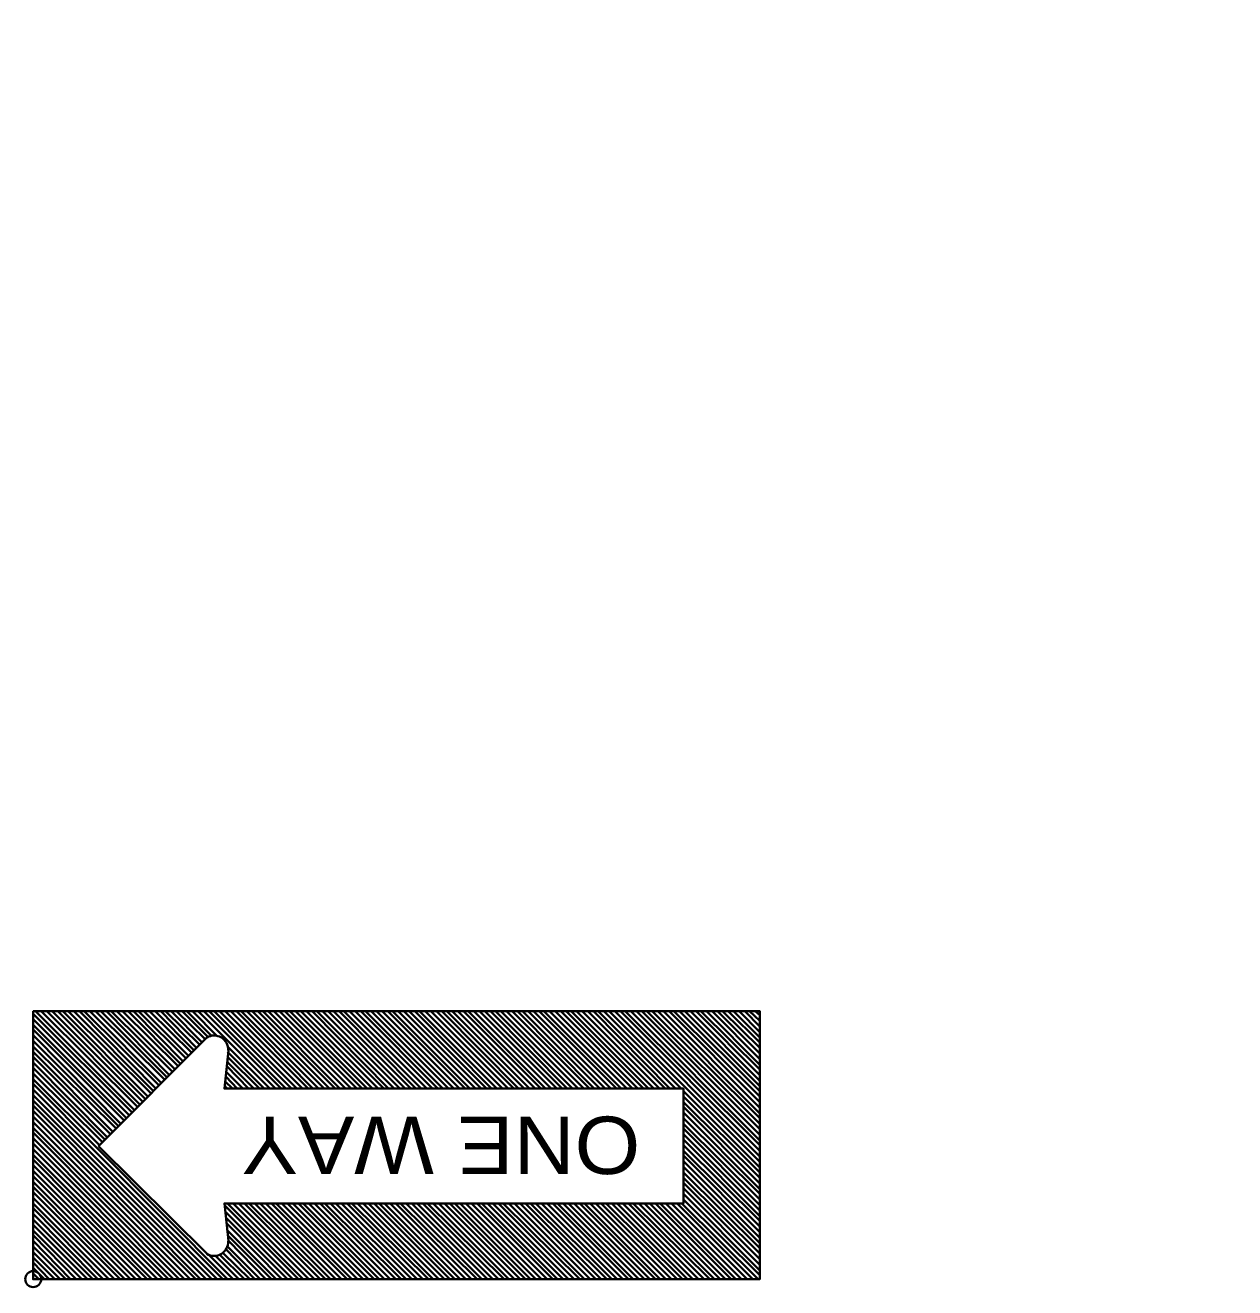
# Model space of a CAD drawing. Extents: x -133 to 547, y -328 to 112.
# Drawn here: x -42.67 to -12.31, y 0.3 to 31.98 of the extents above; entities that cross this region are included whole.
import ezdxf
from ezdxf.enums import TextEntityAlignment as Align

# ---------------------------------------------------------------- set-up
doc = ezdxf.new("R2010")
doc.units = 0
doc.header["$LTSCALE"] = 0.8
doc.header["$PDMODE"] = 32
doc.header["$PDSIZE"] = 0.4
doc.layers.add('1', color=7, linetype='Continuous', lineweight=35)

msp = doc.modelspace()

# ---------------------------------------------------------------- linework, layer by layer
at = {"layer": '1'}
for p, q in [((-42.474, 7.1764), (-39.994, 4.6964)), ((-42.474, 7.0364), (-40.074, 4.6364)), ((-42.414, 7.2364), (-39.934, 4.7564)), ((-42.274, 7.2364), (-39.854, 4.8364)), ((-42.134, 7.2364), (-39.794, 4.8964)), ((-41.994, 7.2364), (-39.734, 4.9764)), ((-41.854, 7.2364), (-39.654, 5.0364)), ((-41.734, 7.2364), (-39.594, 5.0964)), ((-41.594, 7.2364), (-39.514, 5.1764)), ((-41.454, 7.2364), (-39.454, 5.2364)), ((-41.314, 7.2364), (-39.394, 5.2964)), ((-41.194, 7.2364), (-39.314, 5.3764)), ((-41.054, 7.2364), (-39.254, 5.4364)), ((-40.914, 7.2364), (-39.174, 5.5164)), ((-40.774, 7.2364), (-39.114, 5.5764)), ((-40.634, 7.2364), (-39.054, 5.6364)), ((-40.514, 7.2364), (-38.974, 5.7164)), ((-40.374, 7.2364), (-38.914, 5.7764)), ((-40.234, 7.2364), (-38.834, 5.8564)), ((-40.094, 7.2364), (-38.774, 5.9164)), ((-39.954, 7.2364), (-38.714, 5.9764)), ((-39.834, 7.2364), (-38.634, 6.0564)), ((-39.694, 7.2364), (-38.574, 6.1164)), ((-39.554, 7.2364), (-38.494, 6.1964)), ((-39.414, 7.2364), (-38.434, 6.2564)), ((-39.274, 7.2364), (-38.374, 6.3164)), ((-39.154, 7.2364), (-38.294, 6.3964)), ((-39.014, 7.2364), (-38.234, 6.4564)), ((-38.874, 7.2364), (-38.154, 6.5364)), ((-38.734, 7.2364), (-38.094, 6.5964)), ((-38.614, 7.2364), (-37.994, 6.6164)), ((-38.474, 7.2364), (-37.854, 6.6164)), ((-38.334, 7.2364), (-36.394, 5.2964)), ((-38.194, 7.2364), (-36.254, 5.2964)), ((-38.054, 7.2364), (-36.134, 5.2964)), ((-37.934, 7.2364), (-35.994, 5.2964)), ((-37.794, 7.2364), (-35.854, 5.2964)), ((-37.654, 7.2364), (-35.714, 5.2964)), ((-37.514, 7.2364), (-35.574, 5.2964)), ((-37.374, 7.2364), (-35.454, 5.2964)), ((-37.254, 7.2364), (-35.314, 5.2964)), ((-37.114, 7.2364), (-35.174, 5.2964)), ((-36.974, 7.2364), (-35.034, 5.2964)), ((-36.834, 7.2364), (-34.894, 5.2964)), ((-36.714, 7.2364), (-34.774, 5.2964)), ((-36.574, 7.2364), (-34.634, 5.2964)), ((-36.434, 7.2364), (-34.494, 5.2964)), ((-36.294, 7.2364), (-34.354, 5.2964)), ((-36.154, 7.2364), (-34.214, 5.2964)), ((-36.034, 7.2364), (-34.094, 5.2964)), ((-35.894, 7.2364), (-33.954, 5.2964)), ((-35.754, 7.2364), (-33.814, 5.2964)), ((-35.614, 7.2364), (-33.674, 5.2964)), ((-35.474, 7.2364), (-33.554, 5.2964)), ((-35.354, 7.2364), (-33.414, 5.2964)), ((-35.214, 7.2364), (-33.274, 5.2964)), ((-35.074, 7.2364), (-33.134, 5.2964)), ((-34.934, 7.2364), (-32.994, 5.2964)), ((-34.794, 7.2364), (-32.874, 5.2964)), ((-34.674, 7.2364), (-32.734, 5.2964)), ((-34.534, 7.2364), (-32.594, 5.2964)), ((-34.394, 7.2364), (-32.454, 5.2964)), ((-34.254, 7.2364), (-32.314, 5.2964)), ((-34.134, 7.2364), (-32.194, 5.2964)), ((-33.994, 7.2364), (-32.054, 5.2964)), ((-33.854, 7.2364), (-31.914, 5.2964)), ((-33.714, 7.2364), (-31.774, 5.2964)), ((-33.574, 7.2364), (-31.634, 5.2964)), ((-33.454, 7.2364), (-31.514, 5.2964)), ((-33.314, 7.2364), (-31.374, 5.2964)), ((-33.174, 7.2364), (-31.234, 5.2964)), ((-33.034, 7.2364), (-31.094, 5.2964)), ((-32.894, 7.2364), (-30.974, 5.2964)), ((-32.774, 7.2364), (-30.834, 5.2964)), ((-32.634, 7.2364), (-30.694, 5.2964)), ((-32.494, 7.2364), (-30.554, 5.2964)), ((-32.354, 7.2364), (-30.414, 5.2964)), ((-32.214, 7.2364), (-30.294, 5.2964)), ((-32.094, 7.2364), (-30.154, 5.2964)), ((-31.954, 7.2364), (-30.014, 5.2964)), ((-31.814, 7.2364), (-29.874, 5.2964)), ((-31.674, 7.2364), (-29.734, 5.2964)), ((-31.554, 7.2364), (-29.614, 5.2964)), ((-31.414, 7.2364), (-29.474, 5.2964)), ((-31.274, 7.2364), (-29.334, 5.2964)), ((-31.134, 7.2364), (-29.194, 5.2964)), ((-30.994, 7.2364), (-29.074, 5.2964)), ((-30.874, 7.2364), (-28.934, 5.2964)), ((-30.734, 7.2364), (-28.794, 5.2964)), ((-30.594, 7.2364), (-28.654, 5.2964)), ((-30.454, 7.2364), (-28.514, 5.2964)), ((-30.314, 7.2364), (-28.394, 5.2964)), ((-30.194, 7.2364), (-28.254, 5.2964)), ((-30.054, 7.2364), (-28.114, 5.2964)), ((-29.914, 7.2364), (-27.974, 5.2964)), ((-29.774, 7.2364), (-27.834, 5.2964)), ((-29.654, 7.2364), (-27.714, 5.2964)), ((-29.514, 7.2364), (-27.574, 5.2964)), ((-29.374, 7.2364), (-27.434, 5.2964)), ((-29.234, 7.2364), (-27.294, 5.2964)), ((-29.094, 7.2364), (-27.154, 5.2964)), ((-28.974, 7.2364), (-27.034, 5.2964)), ((-28.834, 7.2364), (-26.894, 5.2964)), ((-28.694, 7.2364), (-26.754, 5.2964)), ((-28.554, 7.2364), (-26.614, 5.2964)), ((-28.414, 7.2364), (-26.494, 5.2964)), ((-28.294, 7.2364), (-26.354, 5.2964)), ((-28.154, 7.2364), (-26.214, 5.2964)), ((-28.014, 7.2364), (-24.234, 3.4564)), ((-27.874, 7.2364), (-24.234, 3.5964)), ((-27.734, 7.2364), (-24.234, 3.7364)), ((-27.614, 7.2364), (-24.234, 3.8764)), ((-27.474, 7.2364), (-24.234, 3.9964)), ((-27.334, 7.2364), (-24.234, 4.1364)), ((-27.194, 7.2364), (-24.234, 4.2764)), ((-27.074, 7.2364), (-24.234, 4.4164)), ((-26.934, 7.2364), (-24.234, 4.5564)), ((-26.794, 7.2364), (-24.234, 4.6764)), ((-26.654, 7.2364), (-24.234, 4.8164)), ((-26.514, 7.2364), (-24.234, 4.9564)), ((-26.394, 7.2364), (-24.234, 5.0964)), ((-26.254, 7.2364), (-24.234, 5.2364)), ((-26.114, 7.2364), (-24.234, 5.3564)), ((-25.974, 7.2364), (-24.234, 5.4964)), ((-25.834, 7.2364), (-24.234, 5.6364)), ((-25.714, 7.2364), (-24.234, 5.7764)), ((-25.574, 7.2364), (-24.234, 5.8964)), ((-25.434, 7.2364), (-24.234, 6.0364)), ((-25.294, 7.2364), (-24.234, 6.1764)), ((-25.174, 7.2364), (-24.234, 6.3164)), ((-25.034, 7.2364), (-24.234, 6.4564)), ((-24.894, 7.2364), (-24.234, 6.5764)), ((-24.754, 7.2364), (-24.234, 6.7164)), ((-24.614, 7.2364), (-24.234, 6.8564)), ((-24.494, 7.2364), (-24.234, 6.9964)), ((-24.354, 7.2364), (-24.234, 7.1364)), ((-42.474, 6.8964), (-40.134, 4.5564)), ((-42.474, 6.7764), (-40.194, 4.4964)), ((-42.474, 6.6364), (-40.274, 4.4164)), ((-42.474, 6.4964), (-40.334, 4.3564)), ((-42.474, 6.3564), (-40.394, 4.2964)), ((-38.114, 6.5764), (-40.834, 3.8564)), ((-37.594, 6.3564), (-36.534, 5.2964)), ((-42.474, 6.2164), (-40.474, 4.2164)), ((-42.474, 6.0964), (-40.534, 4.1564)), ((-37.594, 6.2164), (-36.674, 5.2964)), ((-37.594, 6.0964), (-36.794, 5.2964)), ((-42.474, 5.9564), (-40.614, 4.0764)), ((-42.474, 5.8164), (-40.674, 4.0164)), ((-37.634, 5.7164), (-37.214, 5.2964)), ((-37.614, 5.9764), (-36.934, 5.2964)), ((-37.614, 5.8564), (-37.074, 5.2964)), ((-42.474, 5.6764), (-40.734, 3.9564)), ((-42.474, 5.5364), (-40.814, 3.8764)), ((-42.474, 5.4164), (-37.594, 0.5164)), ((-37.654, 5.4764), (-37.474, 5.2964)), ((-37.634, 5.5964), (-37.354, 5.2964)), ((-42.474, 5.2764), (-37.714, 0.5164)), ((-42.474, 5.1364), (-37.854, 0.5164)), ((-37.654, 5.3564), (-37.614, 5.2964)), ((-26.154, 5.2364), (-24.234, 3.3164)), ((-26.154, 5.0964), (-24.234, 3.1964)), ((-42.474, 4.9964), (-37.994, 0.5164)), ((-42.474, 4.8764), (-38.134, 0.5164)), ((-26.154, 4.9564), (-24.234, 3.0564)), ((-26.154, 4.8364), (-24.234, 2.9164)), ((-42.474, 4.7364), (-38.274, 0.5164)), ((-42.474, 4.5964), (-38.394, 0.5164)), ((-42.474, 4.4564), (-38.534, 0.5164)), ((-26.154, 4.6964), (-24.234, 2.7764)), ((-26.154, 4.5564), (-24.234, 2.6564)), ((-42.474, 4.3164), (-38.674, 0.5164)), ((-42.474, 4.1964), (-38.814, 0.5164)), ((-26.154, 4.4164), (-24.234, 2.5164)), ((-26.154, 4.2964), (-24.234, 2.3764)), ((-26.154, 4.1564), (-24.234, 2.2364)), ((-42.474, 4.0564), (-38.954, 0.5164)), ((-42.474, 3.9164), (-39.074, 0.5164)), ((-40.834, 3.8564), (-38.114, 1.1564)), ((-26.154, 4.0164), (-24.234, 2.0964)), ((-26.154, 3.8764), (-24.234, 1.9764)), ((-42.474, 3.7764), (-39.214, 0.5164)), ((-42.474, 3.6364), (-39.354, 0.5164)), ((-42.474, 3.5164), (-39.494, 0.5164)), ((-26.154, 3.7364), (-24.234, 1.8364)), ((-26.154, 3.6164), (-24.234, 1.6964)), ((-42.474, 3.3764), (-39.614, 0.5164)), ((-42.474, 3.2364), (-39.754, 0.5164)), ((-26.154, 3.4764), (-24.234, 1.5564)), ((-26.154, 3.3364), (-24.234, 1.4164)), ((-26.154, 3.1964), (-24.234, 1.2964)), ((-42.474, 3.0964), (-39.894, 0.5164)), ((-42.474, 2.9564), (-40.034, 0.5164)), ((-26.154, 3.0564), (-24.234, 1.1564)), ((-26.154, 2.9364), (-24.234, 1.0164)), ((-42.474, 2.8364), (-40.174, 0.5164)), ((-42.474, 2.6964), (-40.294, 0.5164)), ((-42.474, 2.5564), (-40.434, 0.5164)), ((-26.154, 2.7964), (-24.234, 0.8764)), ((-26.154, 2.6564), (-24.234, 0.7364)), ((-42.474, 2.4164), (-40.574, 0.5164)), ((-42.474, 2.2964), (-40.714, 0.5164)), ((-37.654, 2.3564), (-35.814, 0.5164)), ((-37.594, 2.4164), (-35.694, 0.5164)), ((-37.454, 2.4164), (-35.554, 0.5164)), ((-37.314, 2.4164), (-35.414, 0.5164)), ((-37.174, 2.4164), (-35.274, 0.5164)), ((-37.054, 2.4164), (-35.134, 0.5164)), ((-36.914, 2.4164), (-35.014, 0.5164)), ((-36.774, 2.4164), (-34.874, 0.5164)), ((-36.634, 2.4164), (-34.734, 0.5164)), ((-36.494, 2.4164), (-34.594, 0.5164)), ((-36.374, 2.4164), (-34.474, 0.5164)), ((-36.234, 2.4164), (-34.334, 0.5164)), ((-36.094, 2.4164), (-34.194, 0.5164)), ((-35.954, 2.4164), (-34.054, 0.5164)), ((-35.814, 2.4164), (-33.914, 0.5164)), ((-35.694, 2.4164), (-33.794, 0.5164)), ((-35.554, 2.4164), (-33.654, 0.5164)), ((-35.414, 2.4164), (-33.514, 0.5164)), ((-35.274, 2.4164), (-33.374, 0.5164)), ((-35.154, 2.4164), (-33.234, 0.5164)), ((-35.014, 2.4164), (-33.114, 0.5164)), ((-34.874, 2.4164), (-32.974, 0.5164)), ((-34.734, 2.4164), (-32.834, 0.5164)), ((-34.594, 2.4164), (-32.694, 0.5164)), ((-34.474, 2.4164), (-32.554, 0.5164)), ((-34.334, 2.4164), (-32.434, 0.5164)), ((-34.194, 2.4164), (-32.294, 0.5164)), ((-34.054, 2.4164), (-32.154, 0.5164)), ((-33.914, 2.4164), (-32.014, 0.5164)), ((-33.794, 2.4164), (-31.894, 0.5164)), ((-33.654, 2.4164), (-31.754, 0.5164)), ((-33.514, 2.4164), (-31.614, 0.5164)), ((-33.374, 2.4164), (-31.474, 0.5164)), ((-33.254, 2.4164), (-31.334, 0.5164)), ((-33.114, 2.4164), (-31.214, 0.5164)), ((-32.974, 2.4164), (-31.074, 0.5164)), ((-32.834, 2.4164), (-30.934, 0.5164)), ((-32.694, 2.4164), (-30.794, 0.5164)), ((-32.574, 2.4164), (-30.654, 0.5164)), ((-32.434, 2.4164), (-30.534, 0.5164)), ((-32.294, 2.4164), (-30.394, 0.5164)), ((-32.154, 2.4164), (-30.254, 0.5164)), ((-32.014, 2.4164), (-30.114, 0.5164)), ((-31.894, 2.4164), (-29.994, 0.5164)), ((-31.754, 2.4164), (-29.854, 0.5164)), ((-31.614, 2.4164), (-29.714, 0.5164)), ((-31.474, 2.4164), (-29.574, 0.5164)), ((-31.334, 2.4164), (-29.434, 0.5164)), ((-31.214, 2.4164), (-29.314, 0.5164)), ((-31.074, 2.4164), (-29.174, 0.5164)), ((-30.934, 2.4164), (-29.034, 0.5164)), ((-30.794, 2.4164), (-28.894, 0.5164)), ((-30.674, 2.4164), (-28.754, 0.5164)), ((-30.534, 2.4164), (-28.634, 0.5164)), ((-30.394, 2.4164), (-28.494, 0.5164)), ((-30.254, 2.4164), (-28.354, 0.5164)), ((-30.114, 2.4164), (-28.214, 0.5164)), ((-29.994, 2.4164), (-28.074, 0.5164)), ((-29.854, 2.4164), (-27.954, 0.5164)), ((-29.714, 2.4164), (-27.814, 0.5164)), ((-29.574, 2.4164), (-27.674, 0.5164)), ((-29.434, 2.4164), (-27.534, 0.5164)), ((-29.314, 2.4164), (-27.414, 0.5164)), ((-29.174, 2.4164), (-27.274, 0.5164)), ((-29.034, 2.4164), (-27.134, 0.5164)), ((-28.894, 2.4164), (-26.994, 0.5164)), ((-28.754, 2.4164), (-26.854, 0.5164)), ((-28.634, 2.4164), (-26.734, 0.5164)), ((-28.494, 2.4164), (-26.594, 0.5164)), ((-28.354, 2.4164), (-26.454, 0.5164)), ((-28.214, 2.4164), (-26.314, 0.5164)), ((-28.094, 2.4164), (-26.174, 0.5164)), ((-27.954, 2.4164), (-26.054, 0.5164)), ((-27.814, 2.4164), (-25.914, 0.5164)), ((-27.674, 2.4164), (-25.774, 0.5164)), ((-27.534, 2.4164), (-25.634, 0.5164)), ((-27.414, 2.4164), (-25.494, 0.5164)), ((-27.274, 2.4164), (-25.374, 0.5164)), ((-27.134, 2.4164), (-25.234, 0.5164)), ((-26.994, 2.4164), (-25.094, 0.5164)), ((-26.854, 2.4164), (-24.954, 0.5164)), ((-26.734, 2.4164), (-24.834, 0.5164)), ((-26.594, 2.4164), (-24.694, 0.5164)), ((-26.454, 2.4164), (-24.554, 0.5164)), ((-26.314, 2.4164), (-24.414, 0.5164)), ((-26.194, 2.4164), (-24.274, 0.5164)), ((-26.154, 2.5164), (-24.234, 0.6164)), ((-42.474, 2.1564), (-40.854, 0.5164)), ((-42.474, 2.0164), (-40.974, 0.5164)), ((-37.654, 2.2164), (-35.954, 0.5164)), ((-37.634, 2.0564), (-36.094, 0.5164)), ((-37.614, 1.9164), (-36.234, 0.5164)), ((-42.474, 1.8764), (-41.114, 0.5164)), ((-42.474, 1.7364), (-41.254, 0.5164)), ((-42.474, 1.6164), (-41.394, 0.5164)), ((-37.614, 1.7564), (-36.374, 0.5164)), ((-37.594, 1.6164), (-36.494, 0.5164)), ((-42.474, 1.4764), (-41.534, 0.5164)), ((-42.474, 1.3364), (-41.654, 0.5164)), ((-37.594, 1.3364), (-36.774, 0.5164)), ((-37.574, 1.4764), (-36.634, 0.5164)), ((-42.474, 1.1964), (-41.794, 0.5164)), ((-42.474, 1.0564), (-41.934, 0.5164)), ((-38.054, 1.1164), (-37.454, 0.5164)), ((-37.894, 1.0964), (-37.314, 0.5164)), ((-37.794, 1.1364), (-37.174, 0.5164)), ((-37.714, 1.1764), (-37.034, 0.5164)), ((-37.634, 1.2564), (-36.914, 0.5164)), ((-42.474, 0.9364), (-42.074, 0.5164)), ((-42.474, 0.7964), (-42.194, 0.5164)), ((-42.474, 0.6564), (-42.334, 0.5164))]:
    msp.add_line(p, q, dxfattribs=at)
msp.add_lwpolyline([(-42.474, 0.5164), (-24.234, 0.5164), (-24.234, 7.2364), (-42.474, 7.2364)], close=True, dxfattribs=at)
msp.add_lwpolyline([(-37.574, 1.4764), (-37.674, 2.4164), (-26.154, 2.4164), (-26.154, 5.2964), (-37.674, 5.2964), (-37.574, 6.2564)], dxfattribs=at)
at = {"layer": '1', "lineweight": 53}
msp.add_arc((-16.0081, 31.9802), 50, 270, 0, dxfattribs=at)
at = {"layer": '1'}
for centre, start, end in [((-37.9317, 6.2803), 356.63551, 121.23355), ((-37.9317, 1.4467), 238.76645, 3.36449)]:
    msp.add_arc(centre, 0.3492, start, end, dxfattribs=at)
msp.add_point((-42.474, 0.5164), dxfattribs=at)

# ---------------------------------------------------------------- texts
at = {"layer": '1', "width": 1.1}
msp.add_text('ONE WAY', height=1.44, rotation=180, dxfattribs=at).set_placement((-32.2397, 4.5947), align=Align.CENTER)

doc.saveas('drawing.dxf')
